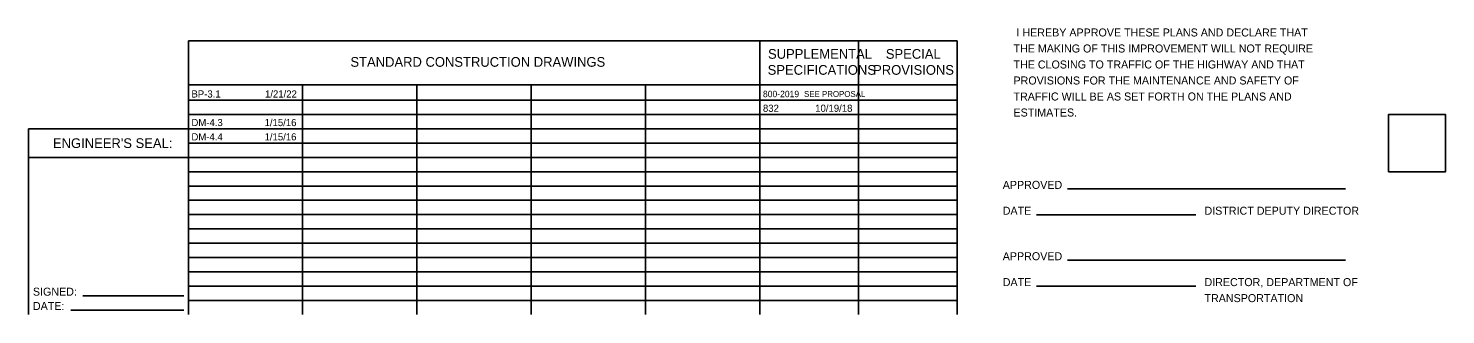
# Model space of a CAD drawing. Extents: x 0 to 68.9, y -26.1 to 22.
# Drawn here: x 44.08 to 68.88, y 0.5 to 5.51 of the extents above; entities that cross this region are included whole.
import ezdxf

# ---------------------------------------------------------------- set-up
doc = ezdxf.new("R2010")
doc.units = 0
doc.layers.add('SH_Data', color=7, linetype='Continuous')
doc.layers.add('SH_Text', color=7, linetype='Continuous')

msp = doc.modelspace()

# ---------------------------------------------------------------- linework, layer by layer
at = {"layer": 'SH_Data'}
for p, q in [((46.884, 5.292), (60.334, 5.292)), ((46.884, 0.5), (46.884, 5.292)), ((56.884, 0.5), (56.884, 5.292)), ((58.609, 0.5), (58.609, 5.292)), ((60.334, 0.5), (60.334, 5.292)), ((46.884, 4.521), (60.334, 4.521)), ((48.884, 0.5), (48.884, 4.521)), ((50.884, 0.5), (50.884, 4.521)), ((52.884, 0.5), (52.884, 4.521)), ((54.884, 0.5), (54.884, 4.521)), ((46.884, 4.25), (60.334, 4.25)), ((46.884, 4), (60.334, 4)), ((44.084, 0.5), (44.084, 3.75)), ((44.084, 3.75), (46.884, 3.75)), ((46.884, 3.75), (60.334, 3.75)), ((46.884, 3.5), (60.334, 3.5)), ((44.084, 3.25), (46.884, 3.25)), ((46.884, 3.25), (60.334, 3.25)), ((46.884, 3), (60.334, 3)), ((46.884, 2.75), (60.334, 2.75)), ((46.884, 2.5), (60.334, 2.5)), ((62.269, 2.7), (67.134, 2.7)), ((46.884, 2.25), (60.334, 2.25)), ((61.725, 2.248), (64.512, 2.248)), ((46.884, 2), (60.334, 2)), ((46.884, 1.75), (60.334, 1.75)), ((46.884, 1.5), (60.334, 1.5)), ((46.884, 1.25), (60.334, 1.25)), ((62.269, 1.452), (67.134, 1.452)), ((46.884, 1), (60.334, 1)), ((61.725, 0.999), (64.512, 0.999)), ((46.884, 0.75), (60.334, 0.75))]:
    msp.add_line(p, q, dxfattribs=at)
msp.add_lwpolyline([(67.884, 3), (68.884, 3), (68.884, 4), (67.884, 4)], close=True, dxfattribs=at)
at = {"layer": 'SH_Text'}
for p, q in [((45.035, 0.832), (46.805, 0.832)), ((44.828, 0.581), (46.805, 0.581))]:
    msp.add_line(p, q, dxfattribs=at)

# ---------------------------------------------------------------- texts
at = {"layer": 'SH_Data'}
for s, p in [(' I HEREBY APPROVE THESE PLANS AND DECLARE THAT', (61.322, 5.366)), ('THE MAKING OF THIS IMPROVEMENT WILL NOT REQUIRE', (61.322, 5.086)), ('THE CLOSING TO TRAFFIC OF THE HIGHWAY AND THAT', (61.322, 4.806)), ('PROVISIONS FOR THE MAINTENANCE AND SAFETY OF', (61.322, 4.526)), ('TRAFFIC WILL BE AS SET FORTH ON THE PLANS AND', (61.322, 4.246)), ('ESTIMATES.', (61.322, 3.966))]:
    msp.add_text(s, height=0.14, dxfattribs=at).set_placement(p)
at = {"layer": 'SH_Text'}
for s, height, p in [('STANDARD CONSTRUCTION DRAWINGS', 0.17, (49.72, 4.836)), ('SUPPLEMENTAL', 0.17, (57.027, 4.976)), ('SPECIAL', 0.17, (59.088, 4.976)), ('SPECIFICATIONS', 0.17, (57.021, 4.696)), ('PROVISIONS', 0.17, (58.866, 4.696)), ('BP-3.1', 0.125, (46.938, 4.298)), ('1/21/22', 0.125, (48.225, 4.298)), ('800-2019', 0.112, (56.938, 4.304)), ('SEE PROPOSAL', 0.10296, (57.658, 4.309)), ('832', 0.125, (56.938, 4.048)), ('10/19/18', 0.125, (57.853, 4.048)), ('DM-4.3', 0.125, (46.938, 3.798)), ('1/15/16', 0.125, (48.218, 3.798)), ("ENGINEER'S SEAL:", 0.17, (44.515, 3.415)), ('DM-4.4', 0.125, (46.938, 3.548)), ('1/15/16', 0.125, (48.218, 3.548)), ('APPROVED', 0.14, (61.134, 2.7)), ('DATE', 0.14, (61.134, 2.248)), ('DISTRICT DEPUTY DIRECTOR', 0.14, (64.664, 2.248)), ('APPROVED', 0.14, (61.134, 1.452)), ('DATE', 0.14, (61.134, 0.999)), ('DIRECTOR, DEPARTMENT OF', 0.14, (64.664, 0.999)), ('SIGNED:', 0.14, (44.164, 0.832)), ('TRANSPORTATION', 0.14, (64.664, 0.719)), ('DATE:', 0.14, (44.164, 0.581))]:
    msp.add_text(s, height=height, dxfattribs=at).set_placement(p)

doc.saveas('drawing.dxf')
